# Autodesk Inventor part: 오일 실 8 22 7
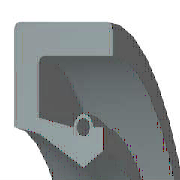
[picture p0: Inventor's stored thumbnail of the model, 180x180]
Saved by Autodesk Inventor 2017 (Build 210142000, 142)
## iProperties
IsCustomPart: 1
Created: 2012-02
Part Number: 오일 실 8 22 7
Material: 고무
Description: 오일-실
Document SubType Name: Modeling
Standard: KS B 2804
Designer: test
Standards Organization: KS
Language: ko-KR
Size Designation: S - 8 22 7
Categories: <MemberInstance><Categories><Category DisplayName="샤프트 부품" InternalName="7f7aeb1f-a693-4053-b835-cee3144e0d98" Mnemonic="SHFT"><Category DisplayName="실링" Intern
Density: 0.93 g/cm^3
Appearance: 고무 - 검은색 - 버전 1.1
Author: test
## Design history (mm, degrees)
revolve "본체" stored, may be unused: angle "d17" = 90 deg
revolve "스프링1" stored, may be unused: angle "d18" = 90 deg
body "Solid1"
sketch "스케치1"
  geometry: L1 (0, 11)-(7, 11); L2 (7, 11)-(7, 9.75); L3 (7, 9.75)-(1.75, 9.75); L4 (0, 11)-(0, 6.1); L5 (0, 6.1)-(1.75, 5.75); L6 (1.75, 5.75)-(4.9, 4); L7 (4.9, 4)-(0, 4); L8 (6.3, 4.875)-(6.3, 6.1); L9 (0, 0)-(9.586, 0) reference; L10 (4.9, 4)-(6.3, 4.875); L11 (0, 18)-(0, -3) reference; L12 (-1.917, 0)-(11.503, 0) reference; L13 (4.2, 6.1)-(1.75, 6.59); L14 (1.75, 6.59)-(1.75, 9.75); L15 (6.3, 6.1)-(5.6, 6.1); C1 r 0.455 at (4.9, 6.1); A1 r 0.7 centre (4.9, 6.1) between (5.6, 6.1) and (4.2, 6.1)
  constraints: 26 end point, 5 horizontal alignment, 4 perpendicular, 2 centre point, 2 collinear, 2 horizontal, 2 parallel, 2 point on circle, 2 point on line, 2 vertical alignment, 1 coincident
  dimensions: "d0" = 22 diameter of L1 L9 (= SD2); "d1" = 9.75 diameter of L8.start L9 (= ABDM); "d2" = 1.25 distance of L1.end L2.end (computed from SD); "d3" = 0.91 diameter of C1 (= SPDI); "d4" = 1.4 diameter of A1 (= SPDA); "d5" = 8 diameter of L6.end L9 (= NND); "d6" = 11.5 diameter of L5.end L9 (= TKDM); "d7" = 12.2 diameter of L4.end L9 (= HLDM); "d8" = 4.9 distance from line of C1.centre L4 (= SPDST); "d9" = 6.3 distance between parallel lines of L8 L4 (= SDI); "d10" = 7 distance between parallel lines of L2 L4 (= SWDT); "d12" = 1.75 distance between parallel lines of L14 L4 (= SD)
fillet "모깎기1" dims "d11" = 0.3 (= RR)
other parameters: "SD2" = 22 [user parameter; used in 1 equation term], "SWDT" = 7 [user parameter; used in 1 equation term], "RR" = 0.3 [user parameter; used in 1 equation term], "SD" = 1.75 [user parameter; used in 2 equation terms], "NND" = 8 [user parameter; used in 1 equation term], "SPDA" = 1.4 [user parameter; used in 1 equation term], "SPDI" = 0.91 [user parameter; used in 1 equation term], "TKDM" = 11.5 [user parameter; used in 1 equation term], "HLDM" = 12.2 [user parameter; used in 1 equation term], "ABDM" = 9.75 [user parameter; used in 1 equation term], "SDI" = 6.3 [user parameter; used in 1 equation term], "SPDST" = 4.9 [user parameter; used in 1 equation term], "d13" = 0, "d14" = 0, "d15" = 0, "LAB" = 0.35 [user parameter]
